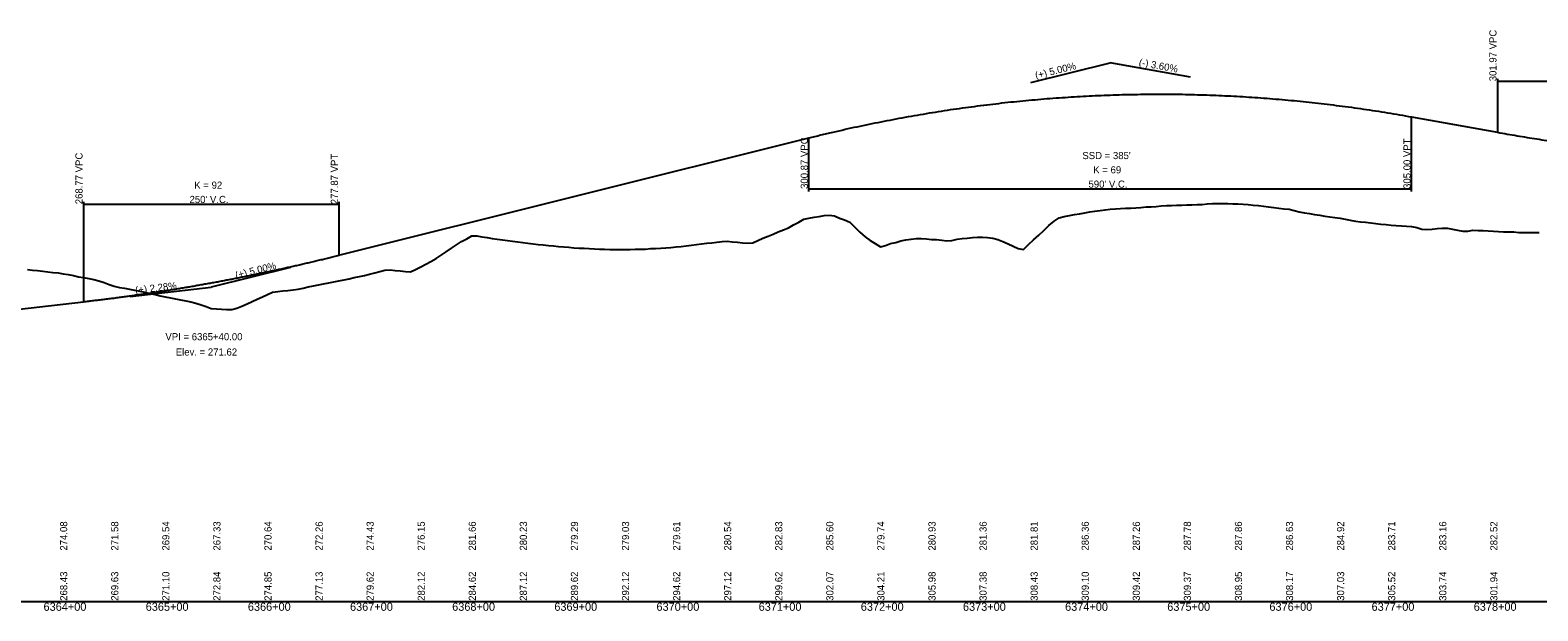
# Model space of a CAD drawing. Extents: x 1838386 to 1955906, y 719739 to 834437.
# Drawn here: x 1952044 to 1953520, y 770980 to 771549 of the extents above; entities that cross this region are included whole.
import ezdxf

# ---------------------------------------------------------------- set-up
doc = ezdxf.new("R2010")
doc.units = 0
for name, color, linetype in [('RD_DDB_GradeTX', 7, 'Continuous'), ('RD_DDB_Profile_EX', 7, 'Continuous'), ('RD_DDB_Profile_Lbl', 7, 'Continuous'), ('RD_DDB_Profile_PR', 7, 'Continuous'), ('RD_DDB_StaTX', 7, 'Continuous'), ('RD_DDB_StripGrade', 7, 'Continuous'), ('RD_DDB_VCLbl', 7, 'Continuous'), ('RD_GPK_Profile_Cell', 7, 'Continuous')]:
    doc.layers.add(name, color=color, linetype=linetype)

msp = doc.modelspace()

# ---------------------------------------------------------------- linework, layer by layer
at = {"layer": 'RD_DDB_GradeTX'}
for p, q in [((1953023.8, 771497.8), (1953101.4, 771517.2)), ((1953180.1, 771503), (1953101.4, 771517.2)), ((1952299, 771316.6), (1952221.4, 771297.2)), ((1952141.9, 771288.2), (1952221.4, 771297.2))]:
    msp.add_line(p, q, dxfattribs=at)
at = {"layer": 'RD_DDB_Profile_EX'}
for points in [[(1952916.4, 771344.9), (1952921.4, 771344.5), (1952926.4, 771344.1), (1952931.4, 771343.8), (1952936.4, 771343.4), (1952941.4, 771342.5), (1952946.4, 771343), (1952951.4, 771344.3), (1952956.4, 771344.9), (1952961.4, 771345.3), (1952966.4, 771345.8), (1952971.4, 771346.3), (1952976.4, 771346.3), (1952981.4, 771346), (1952986.4, 771345.3), (1952991.4, 771344.1), (1952996.4, 771342), (1953001.4, 771339.8), (1953006.4, 771337.5), (1953011.4, 771335.1), (1953016.4, 771334.3), (1953021.4, 771338.9), (1953026.4, 771343.6), (1953031.4, 771348.2), (1953036.4, 771352.9), (1953041.4, 771357.6), (1953046.4, 771362), (1953051.4, 771365.3), (1953056.4, 771366.4), (1953061.4, 771367.5), (1953066.4, 771368.4), (1953071.4, 771369.2), (1953076.4, 771370.1), (1953081.4, 771370.9), (1953086.4, 771371.7), (1953091.4, 771372.4), (1953096.4, 771373.1), (1953101.4, 771373.5), (1953106.4, 771373.9), (1953111.4, 771374.2), (1953116.4, 771374.5), (1953121.4, 771374.8), (1953126.4, 771375.1), (1953131.4, 771375.4), (1953136.4, 771375.8), (1953141.4, 771376.1), (1953146.4, 771376.4), (1953151.4, 771376.8), (1953156.4, 771377.2), (1953161.4, 771377.4), (1953166.4, 771377.6), (1953171.4, 771377.7), (1953176.4, 771377.9), (1953181.4, 771378), (1953186.4, 771378.2), (1953191.4, 771378.3), (1953196.4, 771378.8), (1953201.4, 771379.2), (1953206.4, 771379.2), (1953211.4, 771379.1), (1953216.4, 771379.1), (1953221.4, 771379), (1953226.4, 771378.8), (1953231.4, 771378.5), (1953236.4, 771378.1), (1953241.4, 771377.7), (1953246.4, 771377.1), (1953251.4, 771376.5), (1953256.4, 771375.9), (1953261.4, 771375.3), (1953266.4, 771374.7), (1953271.4, 771374.1), (1953276.4, 771373.5), (1953281.4, 771372.3), (1953286.4, 771371.1), (1953291.4, 771370.1), (1953296.4, 771369.3), (1953301.4, 771368.5), (1953306.4, 771367.7), (1953311.4, 771366.9), (1953316.4, 771366.2), (1953321.4, 771365.4), (1953326.4, 771364.7), (1953331.4, 771363.8), (1953336.4, 771362.8), (1953341.4, 771362), (1953346.4, 771361.4), (1953351.4, 771360.8), (1953356.4, 771360.2), (1953361.4, 771359.6), (1953366.4, 771359.1), (1953371.4, 771358.5), (1953376.4, 771358.1), (1953381.4, 771357.7), (1953386.4, 771357.3), (1953391.4, 771356.9), (1953396.4, 771356.6), (1953401.4, 771355.8), (1953406.4, 771354.2), (1953411.4, 771353.7), (1953416.4, 771354.2)], [(1952416.4, 771312.2), (1952421.4, 771314.7), (1952426.4, 771317.3), (1952431.4, 771319.9), (1952436.4, 771322.5), (1952441.4, 771325.3), (1952446.4, 771328.6), (1952451.4, 771332), (1952456.4, 771335.4), (1952461.4, 771338.7), (1952466.4, 771341.9), (1952471.4, 771344.7), (1952476.4, 771347.5), (1952481.4, 771347.4), (1952486.4, 771346.6), (1952491.4, 771345.8), (1952496.4, 771345), (1952501.4, 771344.2), (1952506.4, 771343.6), (1952511.4, 771343), (1952516.4, 771342.3), (1952521.4, 771341.6), (1952526.4, 771340.9), (1952531.4, 771340.3), (1952536.4, 771339.7), (1952541.4, 771339.1), (1952546.4, 771338.6), (1952551.4, 771338.1), (1952556.4, 771337.6), (1952561.4, 771337.1), (1952566.4, 771336.7), (1952571.4, 771336.3), (1952576.4, 771335.9), (1952581.4, 771335.6), (1952586.4, 771335.3), (1952591.4, 771335), (1952596.4, 771334.8), (1952601.4, 771334.6), (1952606.4, 771334.5), (1952611.4, 771334.3), (1952616.4, 771334.3), (1952621.4, 771334.2), (1952626.4, 771334.3), (1952631.4, 771334.3), (1952636.4, 771334.4), (1952641.4, 771334.5), (1952646.4, 771334.6), (1952651.4, 771335), (1952656.4, 771335.2), (1952661.4, 771335.5), (1952666.4, 771335.9), (1952671.4, 771336.2), (1952676.4, 771336.7), (1952681.4, 771337.2), (1952686.4, 771337.7), (1952691.4, 771338.3), (1952696.4, 771338.9), (1952701.4, 771339.6), (1952706.4, 771340.3), (1952711.4, 771340.8), (1952716.4, 771341.4), (1952721.4, 771342), (1952726.4, 771342.2), (1952731.4, 771341.8), (1952736.4, 771341.3), (1952741.4, 771340.7), (1952746.4, 771340.3), (1952751.4, 771340.8), (1952756.4, 771343), (1952761.4, 771345.1), (1952766.4, 771347.3), (1952771.4, 771349.3), (1952776.4, 771351.3), (1952781.4, 771353.3), (1952786.4, 771355.5), (1952791.4, 771358.3), (1952796.4, 771361), (1952801.4, 771363.8), (1952806.4, 771365), (1952811.4, 771365.8), (1952816.4, 771366.6), (1952821.4, 771367.4), (1952826.4, 771367.8), (1952831.4, 771367.2), (1952836.4, 771364.7), (1952841.4, 771363.1), (1952846.4, 771360.9), (1952851.4, 771356), (1952856.4, 771351.2), (1952861.4, 771346.5), (1952866.4, 771343), (1952871.4, 771340.1), (1952876.4, 771336.7), (1952881.4, 771337.9), (1952886.4, 771340), (1952891.4, 771341.1), (1952896.4, 771342.5), (1952901.4, 771343.5), (1952906.4, 771344.3), (1952911.4, 771344.9), (1952916.4, 771344.9)], [(1953416.4, 771354.2), (1953421.4, 771354.6), (1953426.4, 771355.1), (1953431.4, 771355), (1953436.4, 771354), (1953441.4, 771353.1), (1953446.4, 771352.2), (1953451.4, 771352), (1953456.4, 771353), (1953461.4, 771352.8), (1953466.4, 771352.6), (1953471.4, 771352.3), (1953476.4, 771352), (1953481.4, 771351.7), (1953486.4, 771351.6), (1953491.4, 771351.5), (1953496.4, 771351.3), (1953501.4, 771350.7), (1953506.4, 771350.7), (1953511.4, 771350.7), (1953516.4, 771350.7), (1953521.4, 771350.7)], [(1952041.4, 771314.7), (1952046.4, 771314), (1952051.4, 771313.4), (1952056.4, 771312.8), (1952061.4, 771312.2), (1952066.4, 771311.7), (1952071.4, 771311.2), (1952076.4, 771310.4), (1952081.4, 771309.5), (1952086.4, 771308.6), (1952091.4, 771307.5), (1952096.4, 771306.6), (1952101.4, 771305.7), (1952106.4, 771304.8), (1952111.4, 771303.4), (1952116.4, 771301.7), (1952121.4, 771300), (1952126.4, 771298.2), (1952131.4, 771297), (1952136.4, 771296.1), (1952141.4, 771295.3), (1952146.4, 771294.4), (1952151.4, 771293.3), (1952156.4, 771292.2), (1952161.4, 771291.1), (1952166.4, 771290), (1952171.4, 771288.9), (1952176.4, 771287.9), (1952181.4, 771286.8), (1952186.4, 771285.8), (1952191.4, 771284.8), (1952196.4, 771283.8), (1952201.4, 771282.8), (1952206.4, 771281.7), (1952211.4, 771280), (1952216.4, 771278.2), (1952221.4, 771276.4), (1952226.4, 771276.1), (1952231.4, 771275.8), (1952236.4, 771275.5), (1952241.4, 771275.2), (1952246.4, 771276.5), (1952251.4, 771278.7), (1952256.4, 771281), (1952261.4, 771283.3), (1952266.4, 771285.6), (1952271.4, 771287.9), (1952276.4, 771290.1), (1952281.4, 771292.4), (1952286.4, 771293), (1952291.4, 771293.6), (1952296.4, 771294.1), (1952301.4, 771294.6), (1952306.4, 771295.3), (1952311.4, 771296.3), (1952316.4, 771297.4), (1952321.4, 771298.4), (1952326.4, 771299.4), (1952331.4, 771300.5), (1952336.4, 771301.5), (1952341.4, 771302.5), (1952346.4, 771303.5), (1952351.4, 771304.5), (1952356.4, 771305.5), (1952361.4, 771306.6), (1952366.4, 771307.6), (1952371.4, 771308.7), (1952376.4, 771310.1), (1952381.4, 771311.3), (1952386.4, 771312.5), (1952391.4, 771313.8), (1952396.4, 771314.1), (1952401.4, 771313.7), (1952406.4, 771313.2), (1952411.4, 771312.6), (1952416.4, 771312.2)]]:
    msp.add_lwpolyline(points, dxfattribs=at)
at = {"layer": 'RD_DDB_Profile_PR'}
for p, q in [((1953396.4, 771464.1), (1953480.5, 771449)), ((1952346.4, 771328.5), (1952806.4, 771443.5)), ((1951941.4, 771265.3), (1952096.4, 771283))]:
    msp.add_line(p, q, dxfattribs=at)
for points in [[(1952806.4, 771443.5), (1952818.2, 771446.4), (1952830, 771449.2), (1952841.8, 771451.9), (1952853.6, 771454.5), (1952865.4, 771457), (1952877.2, 771459.3), (1952889, 771461.6), (1952900.8, 771463.8), (1952912.6, 771465.9), (1952924.4, 771467.9), (1952936.2, 771469.8), (1952948, 771471.6), (1952959.8, 771473.2), (1952971.6, 771474.8), (1952983.4, 771476.3), (1952995.2, 771477.7), (1953007, 771479), (1953018.8, 771480.1), (1953030.6, 771481.2), (1953042.4, 771482.2), (1953054.2, 771483), (1953066, 771483.8), (1953077.8, 771484.5), (1953089.6, 771485), (1953101.4, 771485.5), (1953113.2, 771485.9), (1953125, 771486.1), (1953136.8, 771486.3), (1953148.6, 771486.3), (1953160.4, 771486.3), (1953172.2, 771486.2), (1953184, 771485.9), (1953195.8, 771485.6), (1953207.6, 771485.1), (1953219.4, 771484.6), (1953231.2, 771483.9), (1953243, 771483.2), (1953254.8, 771482.3), (1953266.6, 771481.3), (1953278.4, 771480.3), (1953290.2, 771479.1), (1953302, 771477.9), (1953313.8, 771476.5), (1953325.6, 771475), (1953337.4, 771473.5), (1953349.2, 771471.8), (1953361, 771470), (1953372.8, 771468.2), (1953384.6, 771466.2), (1953396.4, 771464.1)], [(1953480.5, 771449), (1953490.1, 771447.3), (1953499.7, 771445.6), (1953509.4, 771444), (1953519, 771442.5), (1953528.7, 771441), (1953538.3, 771439.6), (1953547.9, 771438.3), (1953557.6, 771437), (1953567.2, 771435.7), (1953576.8, 771434.5), (1953586.5, 771433.4), (1953596.1, 771432.3), (1953605.7, 771431.3), (1953615.4, 771430.4), (1953625, 771429.5), (1953634.7, 771428.7), (1953644.3, 771427.9), (1953653.9, 771427.2), (1953663.6, 771426.5), (1953673.2, 771425.9), (1953682.8, 771425.4), (1953692.5, 771424.9), (1953702.1, 771424.4), (1953711.7, 771424.1), (1953721.4, 771423.8), (1953731, 771423.5), (1953740.6, 771423.3), (1953750.3, 771423.2), (1953759.9, 771423.1), (1953769.6, 771423.1), (1953779.2, 771423.1), (1953788.8, 771423.2), (1953798.5, 771423.3), (1953808.1, 771423.6), (1953817.7, 771423.8), (1953827.4, 771424.2), (1953837, 771424.5), (1953846.6, 771425), (1953856.3, 771425.5), (1953865.9, 771426), (1953875.5, 771426.7), (1953885.2, 771427.3), (1953894.8, 771428.1), (1953904.5, 771428.9), (1953914.1, 771429.7), (1953923.7, 771430.6), (1953933.4, 771431.6), (1953943, 771432.6), (1953952.6, 771433.7), (1953962.3, 771434.8)], [(1952096.4, 771283), (1952101.4, 771283.6), (1952106.4, 771284.2), (1952111.4, 771284.8), (1952116.4, 771285.4), (1952121.4, 771286), (1952126.4, 771286.6), (1952131.4, 771287.3), (1952136.4, 771288), (1952141.4, 771288.7), (1952146.4, 771289.4), (1952151.4, 771290.1), (1952156.4, 771290.8), (1952161.4, 771291.5), (1952166.4, 771292.3), (1952171.4, 771293.1), (1952176.4, 771293.8), (1952181.4, 771294.6), (1952186.4, 771295.4), (1952191.4, 771296.3), (1952196.4, 771297.1), (1952201.4, 771297.9), (1952206.4, 771298.8), (1952211.4, 771299.7), (1952216.4, 771300.6), (1952221.4, 771301.5), (1952226.4, 771302.4), (1952231.4, 771303.3), (1952236.4, 771304.3), (1952241.4, 771305.2), (1952246.4, 771306.2), (1952251.4, 771307.2), (1952256.4, 771308.2), (1952261.4, 771309.2), (1952266.4, 771310.2), (1952271.4, 771311.3), (1952276.4, 771312.3), (1952281.4, 771313.4), (1952286.4, 771314.5), (1952291.4, 771315.5), (1952296.4, 771316.7), (1952301.4, 771317.8), (1952306.4, 771318.9), (1952311.4, 771320.1), (1952316.4, 771321.2), (1952321.4, 771322.4), (1952326.4, 771323.6), (1952331.4, 771324.8), (1952336.4, 771326), (1952341.4, 771327.2), (1952346.4, 771328.5)]]:
    msp.add_spline(points, degree=3, dxfattribs=at)
at = {"layer": 'RD_DDB_VCLbl'}
for p, q in [((1953480.5, 771501.5), (1953480.5, 771449)), ((1953480.5, 771499), (1953962.3, 771499)), ((1953396.4, 771391), (1953396.4, 771464.1)), ((1952806.4, 771391), (1952806.4, 771443.5)), ((1952806.4, 771393.5), (1953396.4, 771393.5)), ((1952096.4, 771381), (1952096.4, 771283)), ((1952096.4, 771378.5), (1952346.4, 771378.5)), ((1952346.4, 771381), (1952346.4, 771328.5))]:
    msp.add_line(p, q, dxfattribs=at)
at = {"layer": 'RD_GPK_Profile_Cell'}
msp.add_line((1951406.4, 770989.1), (1955206.4, 770989.1), dxfattribs=at)

# ---------------------------------------------------------------- texts
at = {"layer": 'RD_DDB_GradeTX'}
for s, rotation, p in [('(+) 5.00%', 14.0362, (1953028.8, 771501.1)), ('(-) 3.60%', 349.796, (1953129, 771514.3)), ('(+) 5.00%', 14.0362, (1952245.8, 771305.4)), ('(+) 2.28%', 6.4967, (1952147.3, 771290.8))]:
    msp.add_text(s, height=7, rotation=rotation, dxfattribs=at).set_placement(p)
at = {"layer": 'RD_DDB_Profile_Lbl'}
for s, p in [('VPI = 6365+40.00', (1952176.5, 771245.2)), ('Elev. = 271.62', (1952186.6, 771230.2))]:
    msp.add_text(s, height=7, dxfattribs=at).set_placement(p)
at = {"layer": 'RD_DDB_StaTX'}
for s, p in [('6364+00', (1952057.2, 770980.1)), ('6365+00', (1952157.2, 770980.1)), ('6366+00', (1952257.2, 770980.1)), ('6367+00', (1952357.2, 770980.1)), ('6368+00', (1952457.2, 770980.1)), ('6369+00', (1952557.2, 770980.1)), ('6370+00', (1952657.2, 770980.1)), ('6371+00', (1952757.2, 770980.1)), ('6372+00', (1952857.2, 770980.1)), ('6373+00', (1952957.2, 770980.1)), ('6374+00', (1953057.2, 770980.1)), ('6375+00', (1953157.2, 770980.1)), ('6376+00', (1953257.2, 770980.1)), ('6377+00', (1953357.2, 770980.1)), ('6378+00', (1953457.2, 770980.1))]:
    msp.add_text(s, height=8, dxfattribs=at).set_placement(p)
at = {"layer": 'RD_DDB_StripGrade'}
for s, p in [('301.97 VPC', (1953479.5, 771499)), ('300.87 VPC', (1952805.4, 771393.5)), ('305.00 VPT', (1953395.4, 771393.5)), ('268.77 VPC', (1952095.4, 771378.5)), ('277.87 VPT', (1952345.4, 771378.5)), ('274.08', (1952080.4, 771039.1)), ('271.58', (1952130.4, 771039.1)), ('269.54', (1952180.4, 771039.1)), ('267.33', (1952230.4, 771039.1)), ('270.64', (1952280.4, 771039.1)), ('272.26', (1952330.4, 771039.1)), ('274.43', (1952380.4, 771039.1)), ('276.15', (1952430.4, 771039.1)), ('281.66', (1952480.4, 771039.1)), ('280.23', (1952530.4, 771039.1)), ('279.29', (1952580.4, 771039.1)), ('279.03', (1952630.4, 771039.1)), ('279.61', (1952680.4, 771039.1)), ('280.54', (1952730.4, 771039.1)), ('282.83', (1952780.4, 771039.1)), ('285.60', (1952830.4, 771039.1)), ('279.74', (1952880.4, 771039.1)), ('280.93', (1952930.4, 771039.1)), ('281.36', (1952980.4, 771039.1)), ('281.81', (1953030.4, 771039.1)), ('286.36', (1953080.4, 771039.1)), ('287.26', (1953130.4, 771039.1)), ('287.78', (1953180.4, 771039.1)), ('287.86', (1953230.4, 771039.1)), ('286.63', (1953280.4, 771039.1)), ('284.92', (1953330.4, 771039.1)), ('283.71', (1953380.4, 771039.1)), ('283.16', (1953430.4, 771039.1)), ('282.52', (1953480.4, 771039.1)), ('268.43', (1952080.4, 770989.9)), ('269.63', (1952130.4, 770989.9)), ('271.10', (1952180.4, 770989.9)), ('272.84', (1952230.4, 770989.9)), ('274.85', (1952280.4, 770989.9)), ('277.13', (1952330.4, 770989.9)), ('279.62', (1952380.4, 770989.9)), ('282.12', (1952430.4, 770989.9)), ('284.62', (1952480.4, 770989.9)), ('287.12', (1952530.4, 770989.9)), ('289.62', (1952580.4, 770989.9)), ('292.12', (1952630.4, 770989.9)), ('294.62', (1952680.4, 770989.9)), ('297.12', (1952730.4, 770989.9)), ('299.62', (1952780.4, 770989.9)), ('302.07', (1952830.4, 770989.9)), ('304.21', (1952880.4, 770989.9)), ('305.98', (1952930.4, 770989.9)), ('307.38', (1952980.4, 770989.9)), ('308.43', (1953030.4, 770989.9)), ('309.10', (1953080.4, 770989.9)), ('309.42', (1953130.4, 770989.9)), ('309.37', (1953180.4, 770989.9)), ('308.95', (1953230.4, 770989.9)), ('308.17', (1953280.4, 770989.9)), ('307.03', (1953330.4, 770989.9)), ('305.52', (1953380.4, 770989.9)), ('303.74', (1953430.4, 770989.9)), ('301.94', (1953480.4, 770989.9))]:
    msp.add_text(s, height=7, rotation=90, dxfattribs=at).set_placement(p)
at = {"layer": 'RD_DDB_VCLbl'}
for s, p in [("SSD = 385'", (1953074.1, 771422.7)), ('K = 69', (1953084.8, 771408.7)), ('K = 92', (1952204.8, 771393.7)), ("590' V.C.", (1953080.1, 771394.7)), ("250' V.C.", (1952200.1, 771379.7))]:
    msp.add_text(s, height=7, dxfattribs=at).set_placement(p)

doc.saveas('drawing.dxf')
